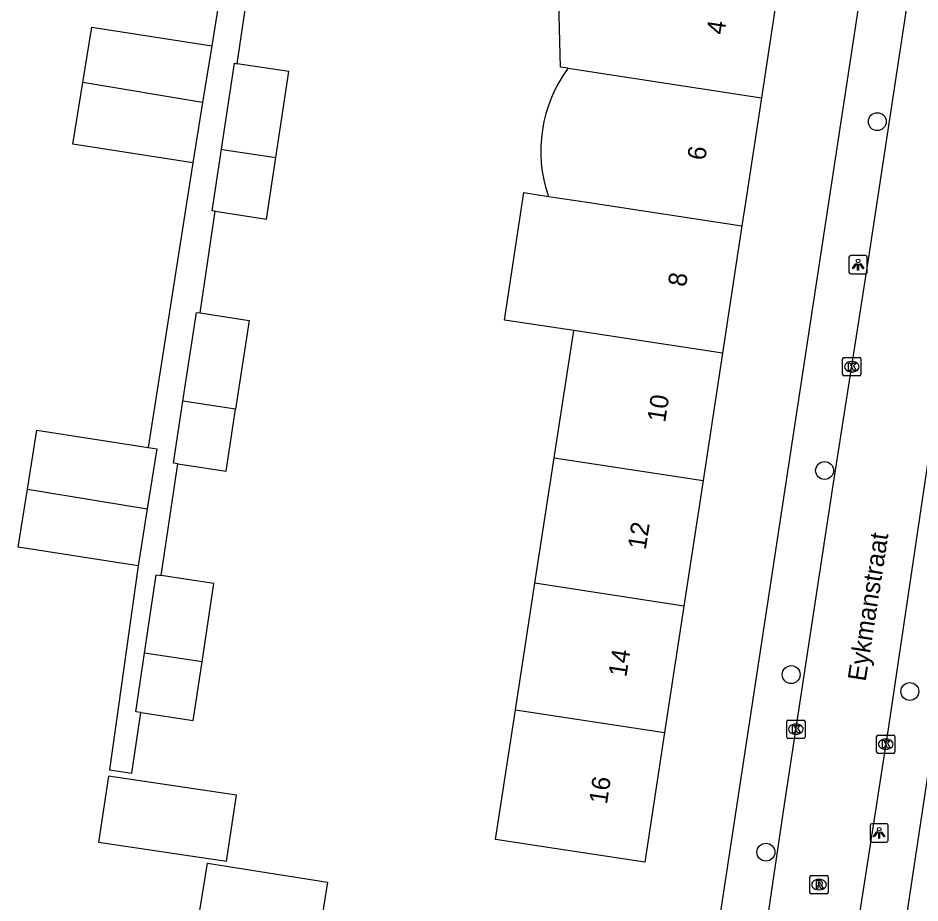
# Model space of a CAD drawing. Extents: x 161486 to 162249, y 379484 to 380829.
# Drawn here: x 161781.86 to 161831.14, y 380461.72 to 380510.09 of the extents above; entities that cross this region are included whole.
import ezdxf

# ---------------------------------------------------------------- set-up
doc = ezdxf.new("R2010")
doc.units = 0
for name, color, linetype in [('IMGEO_Boom', 7, 'Continuous'), ('IMGEO_Kolk', 7, 'Continuous'), ('IMGEO_Lichtpunt', 7, 'Continuous'), ('IMGEO_Openbare_ruimte_label', 7, 'Continuous'), ('IMGEO_Pand', 7, 'Continuous'), ('IMGEO_Pand_nummerreeks', 7, 'Continuous'), ('IMGEO_Rijbaan_lokaal_open', 7, 'Continuous'), ('IMGEO_Rioolput', 7, 'Continuous'), ('IMGEO_Voetpad_open', 7, 'Continuous')]:
    doc.layers.add(name, color=color, linetype=linetype)

msp = doc.modelspace()

# ---------------------------------------------------------------- linework, layer by layer
at = {"layer": 'IMGEO_Boom'}
for centre in [(161828.814, 380504.427), (161825.933, 380485.357), (161824.11, 380474.203), (161830.591, 380473.281), (161822.726, 380464.494)]:
    msp.add_circle(centre, 0.489, dxfattribs=at)
at = {"layer": 'IMGEO_Kolk'}
for p, q in [((161826.919, 380490.604), (161826.919, 380491.456)), ((161826.994, 380491.53), (161827.846, 380491.53)), ((161827.92, 380491.456), (161827.92, 380490.604)), ((161827.407, 380491.31), (161827.432, 380491.31)), ((161827.846, 380490.53), (161826.994, 380490.53)), ((161827.43, 380490.75), (161827.405, 380490.75)), ((161823.864, 380470.791), (161823.864, 380471.643)), ((161823.939, 380471.717), (161824.791, 380471.717)), ((161824.352, 380471.497), (161824.377, 380471.497)), ((161824.865, 380471.643), (161824.865, 380470.791)), ((161824.375, 380470.937), (161824.35, 380470.937)), ((161828.774, 380469.972), (161828.774, 380470.824)), ((161828.849, 380470.898), (161829.701, 380470.898)), ((161829.775, 380470.824), (161829.775, 380469.972)), ((161824.791, 380470.717), (161823.939, 380470.717)), ((161829.262, 380470.678), (161829.287, 380470.678)), ((161829.701, 380469.898), (161828.849, 380469.898)), ((161829.285, 380470.118), (161829.26, 380470.118))]:
    msp.add_line(p, q, dxfattribs=at)
for points in [[(161826.919, 380490.604), (161826.919, 380491.456)], [(161826.994, 380491.53), (161827.846, 380491.53)], [(161827.92, 380491.456), (161827.92, 380490.604)], [(161827.24, 380491.23), (161827.363, 380491.23), (161827.363, 380491.079), (161827.493, 380491.23), (161827.657, 380491.23), (161827.511, 380491.079), (161827.664, 380490.83), (161827.512, 380490.83), (161827.427, 380490.994), (161827.363, 380490.927), (161827.363, 380490.83), (161827.24, 380490.83), (161827.24, 380491.23)], [(161827.846, 380490.53), (161826.994, 380490.53)], [(161823.864, 380470.791), (161823.864, 380471.643)], [(161823.939, 380471.717), (161824.791, 380471.717)], [(161824.185, 380471.417), (161824.308, 380471.417), (161824.308, 380471.266), (161824.438, 380471.417), (161824.602, 380471.417), (161824.456, 380471.266), (161824.609, 380471.017), (161824.457, 380471.017), (161824.372, 380471.181), (161824.308, 380471.114), (161824.308, 380471.017), (161824.185, 380471.017), (161824.185, 380471.417)], [(161824.865, 380471.643), (161824.865, 380470.791)], [(161828.774, 380469.972), (161828.774, 380470.824)], [(161828.849, 380470.898), (161829.701, 380470.898)], [(161829.775, 380470.824), (161829.775, 380469.972)], [(161824.791, 380470.717), (161823.939, 380470.717)], [(161829.095, 380470.598), (161829.218, 380470.598), (161829.218, 380470.447), (161829.348, 380470.598), (161829.512, 380470.598), (161829.366, 380470.447), (161829.519, 380470.198), (161829.367, 380470.198), (161829.282, 380470.362), (161829.218, 380470.295), (161829.218, 380470.198), (161829.095, 380470.198), (161829.095, 380470.598)], [(161829.701, 380469.898), (161828.849, 380469.898)]]:
    msp.add_lwpolyline(points, dxfattribs=at)
for centre, start, end in [((161826.996, 380491.454), 91.552, 178.448), ((161826.996, 380491.454), 91.552, 178.448), ((161827.844, 380491.454), 1.552, 88.448), ((161827.844, 380491.454), 1.552, 88.448), ((161826.996, 380490.606), 181.552, 268.448), ((161826.996, 380490.606), 181.552, 268.448), ((161827.844, 380490.606), 271.552, 358.448), ((161827.844, 380490.606), 271.552, 358.448), ((161823.941, 380471.641), 91.552, 178.448), ((161823.941, 380471.641), 91.552, 178.448), ((161824.789, 380471.641), 1.552, 88.448), ((161824.789, 380471.641), 1.552, 88.448), ((161823.941, 380470.793), 181.552, 268.448), ((161823.941, 380470.793), 181.552, 268.448), ((161824.789, 380470.793), 271.552, 358.448), ((161824.789, 380470.793), 271.552, 358.448), ((161828.851, 380470.822), 91.552, 178.448), ((161828.851, 380470.822), 91.552, 178.448), ((161829.699, 380470.822), 1.552, 88.448), ((161829.699, 380470.822), 1.552, 88.448), ((161828.851, 380469.974), 181.552, 268.448), ((161828.851, 380469.974), 181.552, 268.448), ((161829.699, 380469.974), 271.552, 358.448), ((161829.699, 380469.974), 271.552, 358.448)]:
    msp.add_arc(centre, 0.0765, start, end, dxfattribs=at)
for centre, major_axis, ratio, start_param, end_param in [((161827.406, 380491.03), (-0.387, 0.002), 0.722429, 4.712389, 7.853982), ((161827.431, 380491.03), (-0.39, 0.002), 0.717154, 1.570796, 4.712389), ((161824.351, 380471.217), (-0.387, 0.002), 0.722429, 4.712389, 7.853982), ((161824.376, 380471.217), (-0.39, 0.002), 0.717154, 1.570796, 4.712389), ((161829.261, 380470.398), (-0.387, 0.002), 0.722429, 4.712389, 7.853982), ((161829.286, 380470.398), (-0.39, 0.002), 0.717154, 1.570796, 4.712389)]:
    msp.add_ellipse(centre, major_axis=major_axis, ratio=ratio, start_param=start_param, end_param=end_param, dxfattribs=at)
at = {"layer": 'IMGEO_Lichtpunt'}
for p, q in [((161827.264, 380497.014), (161827.264, 380496.207)), ((161827.264, 380497.014), (161827.264, 380496.207)), ((161828.166, 380497.109), (161827.358, 380497.109)), ((161828.166, 380497.109), (161827.358, 380497.109)), ((161828.26, 380496.207), (161828.26, 380497.014)), ((161828.26, 380496.207), (161828.26, 380497.014)), ((161827.358, 380496.113), (161828.166, 380496.113)), ((161827.358, 380496.113), (161828.166, 380496.113)), ((161828.418, 380465.953), (161828.418, 380465.146)), ((161828.418, 380465.953), (161828.418, 380465.146)), ((161829.32, 380466.048), (161828.512, 380466.048)), ((161829.32, 380466.048), (161828.512, 380466.048)), ((161829.414, 380465.146), (161829.414, 380465.953)), ((161829.414, 380465.146), (161829.414, 380465.953)), ((161828.512, 380465.052), (161829.32, 380465.052)), ((161828.512, 380465.052), (161829.32, 380465.052))]:
    msp.add_line(p, q, dxfattribs=at)
for points in [[(161827.638, 380496.678), (161827.677, 380496.65), (161827.489, 380496.388), (161827.451, 380496.415), (161827.638, 380496.678)], [(161827.74, 380496.63), (161827.787, 380496.63), (161827.787, 380496.308), (161827.74, 380496.308), (161827.74, 380496.63)], [(161827.85, 380496.65), (161827.888, 380496.677), (161828.075, 380496.415), (161828.036, 380496.387), (161827.85, 380496.65)], [(161828.792, 380465.617), (161828.831, 380465.589), (161828.643, 380465.327), (161828.605, 380465.354), (161828.792, 380465.617)], [(161828.894, 380465.569), (161828.941, 380465.569), (161828.941, 380465.247), (161828.894, 380465.247), (161828.894, 380465.569)], [(161829.004, 380465.589), (161829.042, 380465.616), (161829.229, 380465.354), (161829.19, 380465.326), (161829.004, 380465.589)]]:
    msp.add_lwpolyline(points, dxfattribs=at)
for centre in [(161827.763, 380496.812), (161828.917, 380465.751)]:
    msp.add_circle(centre, 0.0994, dxfattribs=at)
for centre, start, end in [((161827.358, 380497.014), 90, 180), ((161827.358, 380497.014), 90, 180), ((161828.166, 380497.014), 0, 90), ((161828.166, 380497.014), 0, 90), ((161827.358, 380496.207), 180, 270), ((161827.358, 380496.207), 180, 270), ((161828.166, 380496.207), 270, 0), ((161828.166, 380496.207), 270, 360), ((161828.512, 380465.953), 90, 180), ((161828.512, 380465.953), 90, 180), ((161829.32, 380465.953), 0, 90), ((161829.32, 380465.953), 0, 90), ((161828.512, 380465.146), 180, 270), ((161828.512, 380465.146), 180, 270), ((161829.32, 380465.146), 270, 0), ((161829.32, 380465.146), 270, 360)]:
    msp.add_arc(centre, 0.0946, start, end, dxfattribs=at)
at = {"layer": 'IMGEO_Pand'}
for points in [[(161811.917, 380507.348), (161811.497, 380507.412), (161811.329, 380514.457), (161812.31, 380514.307)], [(161823.53, 380512.595), (161822.484, 380505.736)], [(161785.398, 380506.557), (161785.887, 380509.598), (161792.446, 380508.566)], [(161792.446, 380508.566), (161791.948, 380505.466)], [(161792.98, 380502.915), (161793.697, 380507.615), (161793.839, 380507.593)], [(161795.948, 380502.462), (161796.665, 380507.162), (161793.839, 380507.593)], [(161811.917, 380507.348), (161822.484, 380505.736)], [(161791.418, 380502.168), (161784.859, 380503.2), (161785.398, 380506.557)], [(161791.948, 380505.466), (161785.398, 380506.557)], [(161822.484, 380505.736), (161821.609, 380500), (161821.415, 380498.729)], [(161791.948, 380505.466), (161791.418, 380502.168)], [(161792.641, 380499.527), (161792.467, 380499.554), (161792.98, 380502.915)], [(161792.98, 380502.915), (161793.14, 380502.891), (161795.948, 380502.462)], [(161792.641, 380499.527), (161795.435, 380499.101), (161795.948, 380502.462)], [(161812.227, 380493.006), (161808.443, 380493.583), (161809.506, 380500.547), (161810.839, 380500.342)], [(161810.839, 380500.342), (161813.084, 380500), (161813.297, 380499.968), (161821.415, 380498.729)], [(161821.415, 380498.729), (161820.353, 380491.766)], [(161790.87, 380489.141), (161791.611, 380494), (161791.816, 380493.969)], [(161791.816, 380493.969), (161794.485, 380493.561), (161793.744, 380488.702)], [(161811.157, 380486.045), (161812.227, 380493.006)], [(161820.353, 380491.766), (161812.227, 380493.006)], [(161820.353, 380491.766), (161819.29, 380484.804)], [(161790.59, 380485.718), (161790.353, 380485.754), (161790.87, 380489.141)], [(161793.744, 380488.702), (161790.87, 380489.141)], [(161790.59, 380485.718), (161793.227, 380485.315), (161793.744, 380488.702)], [(161782.371, 380484.342), (161782.89, 380487.57), (161788.971, 380486.613)], [(161788.971, 380486.613), (161789.449, 380486.538), (161788.922, 380483.26)], [(161810.103, 380479.192), (161811.157, 380486.045)], [(161811.157, 380486.045), (161819.29, 380484.804)], [(161819.29, 380484.804), (161818.245, 380477.949)], [(161788.421, 380480.14), (161781.862, 380481.172), (161782.371, 380484.342)], [(161782.371, 380484.342), (161788.922, 380483.26)], [(161788.922, 380483.26), (161788.421, 380480.14)], [(161788.772, 380475.374), (161789.409, 380479.653), (161789.683, 380479.612)], [(161791.914, 380474.894), (161792.552, 380479.186), (161789.683, 380479.612)], [(161809.041, 380472.282), (161810.103, 380479.192)], [(161818.245, 380477.949), (161810.103, 380479.192)], [(161818.245, 380477.949), (161817.19, 380471.039)], [(161788.57, 380472.122), (161788.295, 380472.163), (161788.772, 380475.374)], [(161791.914, 380474.894), (161788.772, 380475.374)], [(161788.57, 380472.122), (161791.438, 380471.695), (161791.914, 380474.894)], [(161817.19, 380471.039), (161816.109, 380463.952), (161811.167, 380464.706), (161807.952, 380465.196), (161809.041, 380472.282)], [(161809.041, 380472.282), (161817.19, 380471.039)], [(161786.336, 380465.513), (161786.267, 380465.047), (161793.256, 380464.009), (161793.29, 380464.235), (161793.791, 380467.611), (161786.802, 380468.65), (161786.336, 380465.513)], [(161798.772, 380462.855), (161797.744, 380456.457), (161791.185, 380457.489), (161792.213, 380463.887), (161798.772, 380462.855)]]:
    msp.add_lwpolyline(points, dxfattribs=at)
msp.add_arc((161818.022, 380502.823), 7.599, 143.4515, 199.0537, dxfattribs=at)
at = {"layer": 'IMGEO_Rijbaan_lokaal_open'}
for points in [[(161821.471, 380451.732), (161821.655, 380452.898), (161822.073, 380455.75), (161823.193, 380463.396), (161823.737, 380467.105), (161826.407, 380484.559), (161828.338, 380496.887), (161828.809, 380500), (161830.37, 380510.32), (161831.054, 380514.815), (161831.451, 380517.407), (161832.24, 380522.561), (161832.423, 380523.763), (161832.99, 380527.495), (161833.764, 380532.583)], [(161838.629, 380531.844), (161837.587, 380525.413), (161836.396, 380517.62), (161833.702, 380500), (161833.095, 380496.033), (161829.443, 380471.483), (161827.998, 380462.196), (161826.792, 380454.443), (161826.524, 380452.721), (161826.274, 380451.023)]]:
    msp.add_lwpolyline(points, dxfattribs=at)
at = {"layer": 'IMGEO_Rioolput'}
for p, q in [((161825.128, 380462.298), (161825.128, 380463.15)), ((161825.203, 380463.224), (161826.055, 380463.224)), ((161825.616, 380463.004), (161825.641, 380463.004)), ((161826.129, 380463.15), (161826.129, 380462.298)), ((161825.639, 380462.444), (161825.614, 380462.444)), ((161826.055, 380462.224), (161825.203, 380462.224))]:
    msp.add_line(p, q, dxfattribs=at)
for points in [[(161825.128, 380462.298), (161825.128, 380463.15)], [(161825.203, 380463.224), (161826.055, 380463.224)], [(161825.717, 380462.922), (161825.465, 380462.924), (161825.465, 380462.524)], [(161826.129, 380463.15), (161826.129, 380462.298)], [(161825.465, 380462.524), (161825.589, 380462.524), (161825.589, 380462.686), (161825.6, 380462.686)], [(161825.643, 380462.843), (161825.589, 380462.843), (161825.589, 380462.762)], [(161825.589, 380462.762), (161825.641, 380462.762)], [(161825.647, 380462.657), (161825.718, 380462.524), (161825.858, 380462.524), (161825.793, 380462.65)], [(161826.055, 380462.224), (161825.203, 380462.224)]]:
    msp.add_lwpolyline(points, dxfattribs=at)
for centre, radius, start, end in [((161825.205, 380463.148), 0.0765, 91.552, 178.448), ((161825.205, 380463.148), 0.0765, 91.552, 178.448), ((161825.716, 380462.812), 0.109, 350.3612, 89.416), ((161826.053, 380463.148), 0.0765, 1.552, 88.448), ((161826.053, 380463.148), 0.0765, 1.552, 88.448), ((161825.599, 380462.633), 0.0533, 26.0293, 88.6989), ((161825.625, 380462.951), 0.19, 274.7715, 282.9687), ((161825.649, 380462.747), 0.0964, 77.0061, 93.1865), ((161825.663, 380462.804), 0.0378, 276.6634, 79.6772), ((161825.714, 380462.812), 0.112, 277.5842, 350.9817), ((161825.698, 380462.597), 0.108, 29.5134, 73.7905), ((161825.205, 380462.3), 0.0765, 181.552, 268.448), ((161825.205, 380462.3), 0.0765, 181.552, 268.448), ((161826.053, 380462.3), 0.0765, 271.552, 358.448), ((161826.053, 380462.3), 0.0765, 271.552, 358.448)]:
    msp.add_arc(centre, radius, start, end, dxfattribs=at)
for centre, major_axis, ratio, start_param, end_param in [((161825.615, 380462.724), (-0.387, 0.002), 0.722429, 4.712389, 7.853982), ((161825.64, 380462.724), (-0.39, 0.002), 0.717154, 1.570796, 4.712389)]:
    msp.add_ellipse(centre, major_axis=major_axis, ratio=ratio, start_param=start_param, end_param=end_param, dxfattribs=at)
at = {"layer": 'IMGEO_Voetpad_open'}
for points in [[(161794.9, 380523.895), (161792.446, 380508.566)], [(161829.598, 380522.608), (161826.151, 380500), (161816.597, 380437.337)], [(161826.545, 380435.252), (161836.294, 380500), (161839.366, 380520.406)], [(161793.839, 380507.593), (161794.717, 380513.503)], [(161791.418, 380502.168), (161788.971, 380486.613)], [(161791.816, 380493.969), (161792.641, 380499.527)], [(161789.683, 380479.612), (161790.59, 380485.718)], [(161788.421, 380480.14), (161786.854, 380468.998), (161788.079, 380468.816), (161788.57, 380472.122)]]:
    msp.add_lwpolyline(points, dxfattribs=at)

# ---------------------------------------------------------------- texts
at = {"layer": 'IMGEO_Openbare_ruimte_label'}
msp.add_text('Eykmanstraat', height=1, rotation=81.1972, dxfattribs=at).set_placement((161828.175, 380473.796))
at = {"layer": 'IMGEO_Pand_nummerreeks'}
for s, rotation, p in [('4', 81.3257, (161820.454, 380509.141)), ('6', 81.3257, (161819.406, 380502.272)), ('8', 81.3256, (161818.353, 380495.363)), ('10', 81.325, (161817.221, 380487.951)), ('12', 81.325, (161816.159, 380480.991)), ('14', 81.325, (161815.099, 380474.038)), ('16', 81.325, (161814.038, 380467.082))]:
    msp.add_text(s, height=1, rotation=rotation, dxfattribs=at).set_placement(p)

doc.saveas('drawing.dxf')
